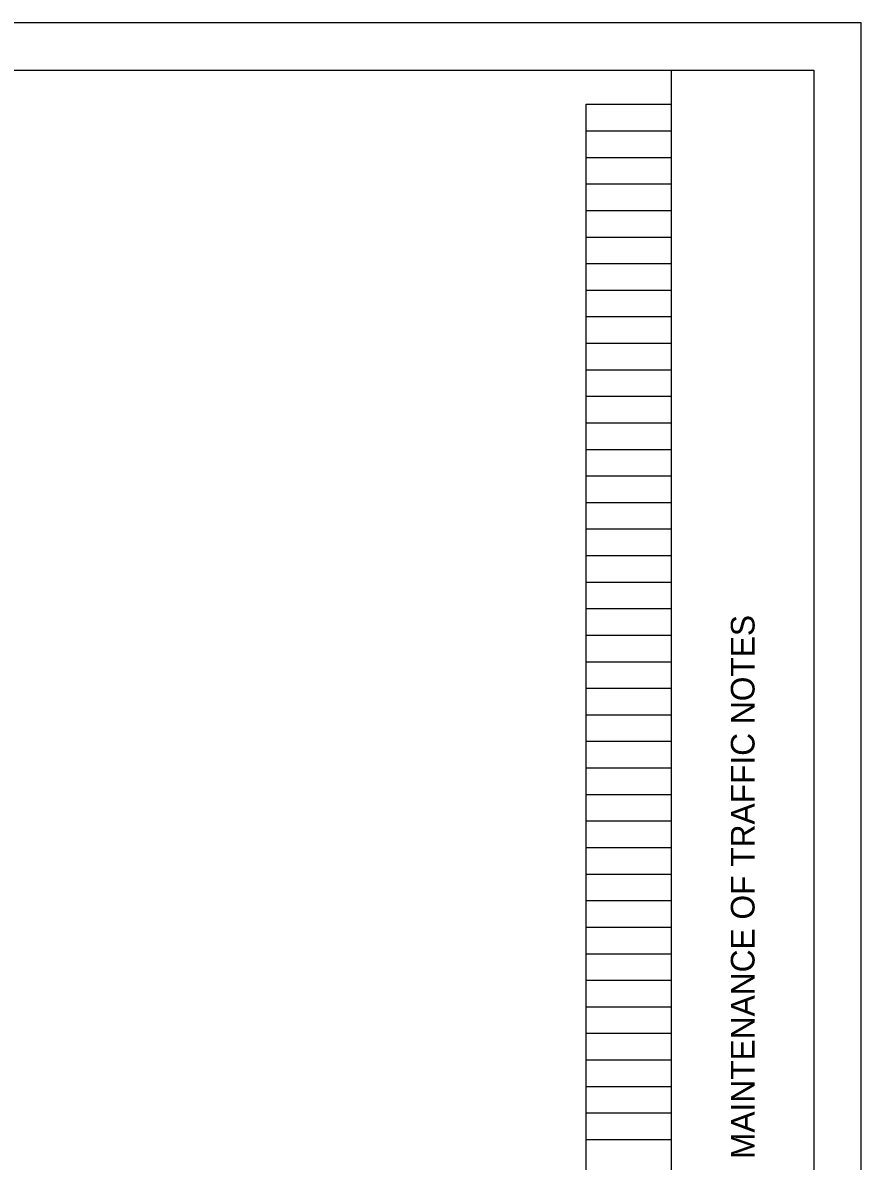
# Model space of a CAD drawing. Extents: x 0 to 1381193, y -3 to 468856.
# Drawn here: x 25.16 to 34, y 9.99 to 22 of the extents above; entities that cross this region are included whole.
import ezdxf

# ---------------------------------------------------------------- set-up
doc = ezdxf.new("R2010")
doc.units = 0
for name, color, linetype in [('SV_P_Mon_Cells_Set', 7, 'Continuous'), ('SV_X_Mon_Cells_Found', 7, 'Continuous'), ('SV_X_Shot_Marker', 7, 'Continuous')]:
    doc.layers.add(name, color=color, linetype=linetype)

msp = doc.modelspace()

# ---------------------------------------------------------------- linework, layer by layer
at = {"layer": 'SV_P_Mon_Cells_Set'}
msp.add_lwpolyline([(0, 0), (34, 0), (34, 22), (0, 22)], close=True, dxfattribs=at)
at = {"layer": 'SV_X_Mon_Cells_Found'}
msp.add_line((32, 0.5), (32, 21.5), dxfattribs=at)
msp.add_lwpolyline([(1.5, 21.5), (33.5, 21.5), (33.5, 0.5), (1.5, 0.5)], close=True, dxfattribs=at)
at = {"layer": 'SV_X_Shot_Marker'}
for p, q in [((31.1, 0.98), (31.1, 21.14)), ((31.1, 21.14), (32, 21.14)), ((32, 0.98), (32, 21.14)), ((31.1, 20.86), (32, 20.86)), ((31.1, 20.58), (32, 20.58)), ((31.1, 20.3), (32, 20.3)), ((31.1, 20.02), (32, 20.02)), ((31.1, 19.74), (32, 19.74)), ((31.1, 19.46), (32, 19.46)), ((31.1, 19.18), (32, 19.18)), ((31.1, 18.9), (32, 18.9)), ((31.1, 18.62), (32, 18.62)), ((31.1, 18.34), (32, 18.34)), ((31.1, 18.06), (32, 18.06)), ((31.1, 17.78), (32, 17.78)), ((31.1, 17.5), (32, 17.5)), ((31.1, 17.22), (32, 17.22)), ((31.1, 16.94), (32, 16.94)), ((31.1, 16.66), (32, 16.66)), ((31.1, 16.38), (32, 16.38)), ((31.1, 16.1), (32, 16.1)), ((31.1, 15.82), (32, 15.82)), ((31.1, 15.54), (32, 15.54)), ((31.1, 15.26), (32, 15.26)), ((31.1, 14.98), (32, 14.98)), ((31.1, 14.7), (32, 14.7)), ((31.1, 14.42), (32, 14.42)), ((31.1, 14.14), (32, 14.14)), ((31.1, 13.86), (32, 13.86)), ((31.1, 13.58), (32, 13.58)), ((31.1, 13.3), (32, 13.3)), ((31.1, 13.02), (32, 13.02)), ((31.1, 12.74), (32, 12.74)), ((31.1, 12.46), (32, 12.46)), ((31.1, 12.18), (32, 12.18)), ((31.1, 11.9), (32, 11.9)), ((31.1, 11.62), (32, 11.62)), ((31.1, 11.34), (32, 11.34)), ((31.1, 11.06), (32, 11.06)), ((31.1, 10.78), (32, 10.78)), ((31.1, 10.5), (32, 10.5)), ((31.1, 10.22), (32, 10.22))]:
    msp.add_line(p, q, dxfattribs=at)

# ---------------------------------------------------------------- texts
msp.add_text('MAINTENANCE OF TRAFFIC NOTES', height=0.25, rotation=90, dxfattribs=at).set_placement((32.875, 10.014))

doc.saveas('drawing.dxf')
